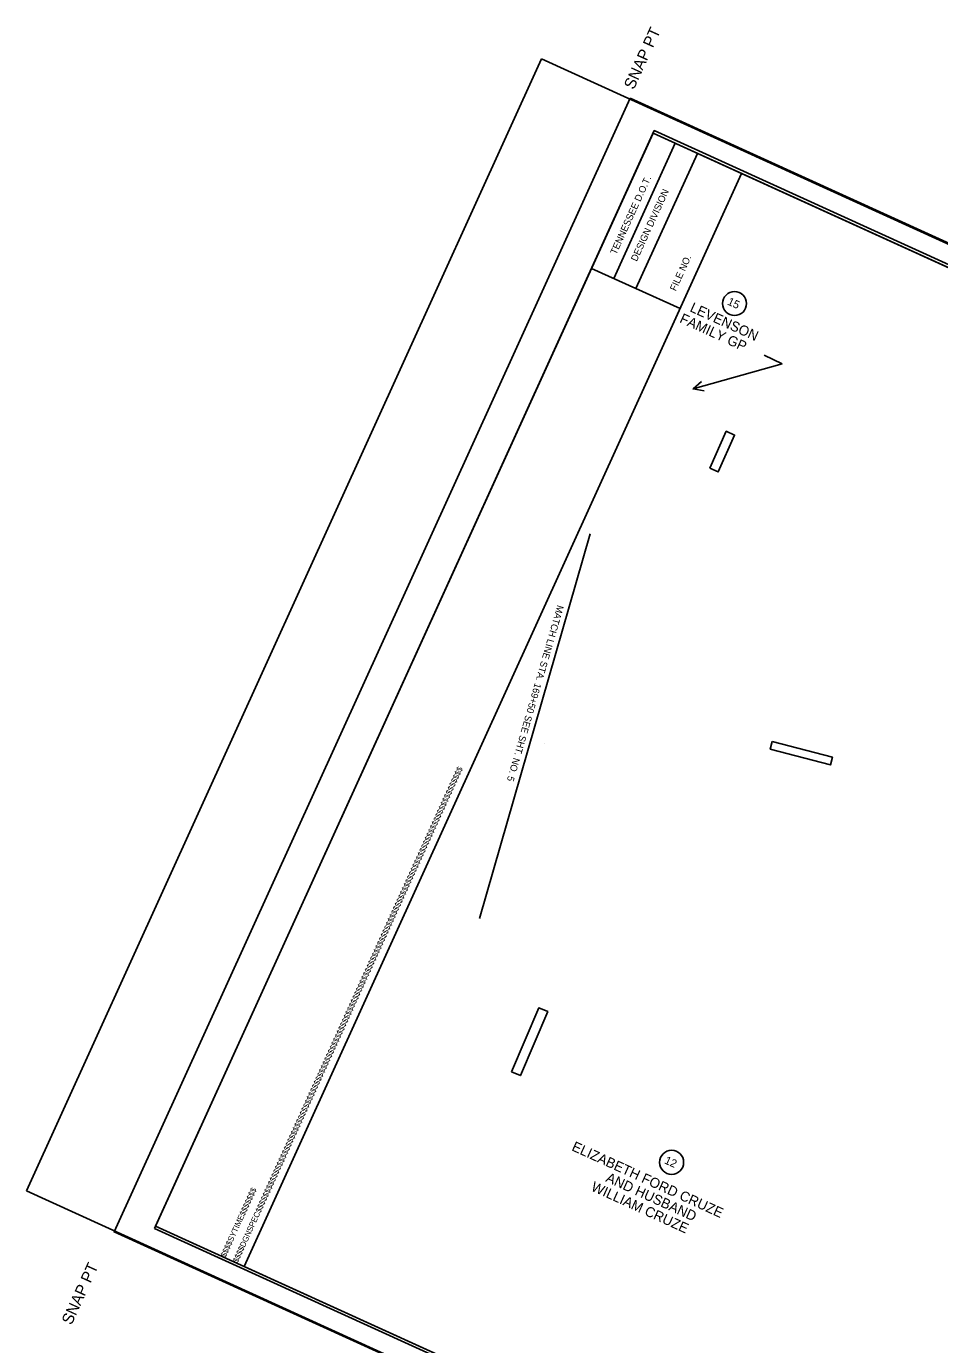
# Model space of a CAD drawing. Extents: x 2628810 to 2630911, y 568379 to 570218.
# Drawn here: x 2628810 to 2629609, y 569065 to 570218 of the extents above; entities that cross this region are included whole.
import ezdxf

# ---------------------------------------------------------------- set-up
doc = ezdxf.new("R2010")
doc.units = 0
for name, color, linetype in [('DESIGN - CENTERLINE - Proposed Text', 7, 'Continuous'), ('DESIGN - SCRATCH - User 1', 7, 'Continuous'), ('DESIGN - SHEET - Corner Text', 7, 'Continuous'), ('DESIGN - SHEET - Light Grid', 7, 'Continuous'), ('DESIGN - SHEET - Linework', 7, 'Continuous'), ('DESIGN - SHEET - Plot Shape', 7, 'Continuous'), ('SURVEY - GROUND - Top of Ground', 7, 'Continuous'), ('SURVEY - PROPERTY - Owners', 7, 'Continuous'), ('SURVEY - PROPERTY - Tract Numbers', 7, 'Continuous')]:
    doc.layers.add(name, color=color, linetype=linetype)

msp = doc.modelspace()

# ---------------------------------------------------------------- linework, layer by layer
at = {"layer": 'DESIGN - CENTERLINE - Proposed Text'}
msp.add_lwpolyline([(2629206.2, 569438), (2629254.5, 569606.2), (2629302.9, 569774.4)], dxfattribs=at)
at = {"layer": 'DESIGN - SCRATCH - User 1'}
msp.add_line((2629263.3, 569590.9), (2629263.3, 569590.9), dxfattribs=at)
at = {"layer": 'DESIGN - SHEET - Light Grid'}
msp.add_lwpolyline([(2628921.9, 569166.8), (2630437.2, 568477), (2630874.3, 569437.1), (2629359, 570127)], close=True, dxfattribs=at)
at = {"layer": 'DESIGN - SHEET - Linework'}
for p, q in [((2628809.8, 569200), (2629260.3, 570189.7)), ((2629260.3, 570189.7), (2630898.6, 569443.9)), ((2629377.3, 570115.9), (2629323.5, 569997.7)), ((2629396.7, 570107.1), (2629342.8, 569988.9)), ((2628809.8, 569200), (2630448, 568454.2))]:
    msp.add_line(p, q, dxfattribs=at)
for points in [[(2629435.3, 570089.5), (2629357.9, 570124.7), (2629304.1, 570006.5), (2629381.5, 569971.3)], [(2629435.3, 570089.5), (2629000.3, 569133.8), (2630433, 568481.6), (2630868.1, 569437.3), (2629435.3, 570089.5)]]:
    msp.add_lwpolyline(points, dxfattribs=at)
at = {"layer": 'DESIGN - SHEET - Plot Shape'}
for points in [[(2629338, 570155.5), (2630885.2, 569451.1), (2630433.8, 568459.6), (2628886.6, 569164)], [(2629357.9, 570124.7), (2630868.1, 569437.3), (2630433, 568481.6), (2628922.9, 569169.1)]]:
    msp.add_lwpolyline(points, close=True, dxfattribs=at)
at = {"layer": 'SURVEY - GROUND - Top of Ground'}
for points in [[(2629407.6, 569831.7), (2629415, 569828.5), (2629429.3, 569860.8), (2629421.9, 569864.1)], [(2629462.2, 569592.7), (2629460.5, 569586), (2629513.1, 569572.3), (2629514.8, 569579)], [(2629234, 569303.9), (2629241.9, 569300.6), (2629265.8, 569356.6), (2629257.9, 569359.9)]]:
    msp.add_lwpolyline(points, close=True, dxfattribs=at)
at = {"layer": 'SURVEY - PROPERTY - Tract Numbers'}
for points in [[(2629471, 569923.2), (2629455, 569930.5)], [(2629393, 569901.1), (2629471, 569923.2)], [(2629402.7, 569899.3), (2629393, 569901.1), (2629400.3, 569907.7)]]:
    msp.add_lwpolyline(points, dxfattribs=at)
for centre in [(2629429.2, 569975.8), (2629374.2, 569224.8)]:
    msp.add_circle(centre, 10.5, dxfattribs=at)

# ---------------------------------------------------------------- texts
at = {"layer": 'DESIGN - CENTERLINE - Proposed Text'}
msp.add_text('MATCH LINE STA. 169+50 SEE SHT. NO. 5', height=6, rotation=253.9554, dxfattribs=at).set_placement((2629274.2, 569712.5))
at = {"layer": 'DESIGN - SHEET - Corner Text'}
for s, height, p in [('  SNAP PT', 10, (2629338, 570155.5)), ('TENNESSEE D.O.T.', 6, (2629325.7, 570018.1)), ('DESIGN DIVISION', 6, (2629343.7, 570012.1)), ('FILE NO.', 6, (2629377.8, 569986.2)), ('$$$$DGNSPEC$$$$$$$$$$$$$$$$$$$$$$$$$$$$$$$$$$$$$$$$$$$$$$$$$$$$$$$$$$$$$$$$$$$$$$$$$$$$$$$$$$$$$$$$$$$$$$$$$$$$$$$$$$$$$$$$$$$', 5.0001, (2628994.6, 569136.5)), ('$$$$SYTIME$$$$$$$', 5, (2628984, 569141.3)), ('SNAP PT  ', 10, (2628849.3, 569082))]:
    msp.add_text(s, height=height, rotation=65.5232, dxfattribs=at).set_placement(p)
at = {"layer": 'SURVEY - PROPERTY - Owners'}
for s, p in [('LEVENSON', (2629389.5, 569969.2)), ('FAMILY GP', (2629380.5, 569959.6)), ('ELIZABETH FORD CRUZE', (2629286.1, 569235.5)), ('AND HUSBAND', (2629315.9, 569208.3)), ('WILLIAM CRUZE', (2629303, 569200.4))]:
    msp.add_text(s, height=8.75, rotation=335.5232, dxfattribs=at).set_placement(p)
at = {"layer": 'SURVEY - PROPERTY - Tract Numbers'}
for s, p in [('15', (2629422.3, 569975.1)), ('12', (2629367.3, 569224.1))]:
    msp.add_text(s, height=7, rotation=335.5232, dxfattribs=at).set_placement(p)

doc.saveas('drawing.dxf')
